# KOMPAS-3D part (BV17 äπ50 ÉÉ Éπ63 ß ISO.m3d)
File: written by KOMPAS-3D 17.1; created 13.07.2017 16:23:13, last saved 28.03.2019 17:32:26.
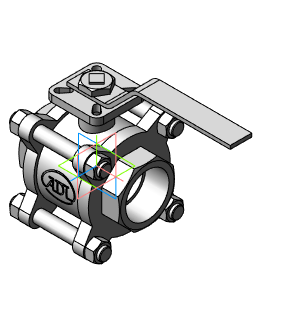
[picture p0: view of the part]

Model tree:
1. Операция без истории:2  (labels: Сталь 20  ГОСТ 1050-88)

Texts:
  DISO1
  DISO2
  BV17 Ду8 1/4" Ру63 с ISO
  BV17 Ду8 СС Ру63 с ISO
  BV17 Ду10 3/8" Ру63 с ISO
  BV17 Ду10 СС Ру63 с ISO
  BV17 Ду15 1/2" Ру63 с ISO
  BV17 Ду15 СС Ру63 с ISO
  BV17 Ду15 ФФ Ру40 с ISO
  BV17 Ду20 3/4" Ру63 с ISO
  BV17 Ду20 СС Ру40 с ISO
  BV17 Ду20 ФФ Ру40 с ISO
  BV17 Ду25 1" Ру63 с ISO
  BV17 Ду25 СС Ру63 с ISO
  BV17 Ду25 ФФ Ру40 с ISO
  BV17 Ду32 1 1/4" Ру63 с ISO
  BV17 Ду32 СС Ру63 с ISO
  BV17 Ду32 ФФ Ру40 с ISO
  BV17 Ду40 1 1/2" Ру63 с ISO
  BV17 Ду40 СС Ру63 с ISO
  BV17 Ду40 ФФ Ру40 с ISO
  BV17 Ду50 2" Ру63 с ISO
  BV17 Ду50 СС Ру63 с ISO
  BV17 Ду50 ФФ Ру40 с ISO
  BV17 Ду65 2 1/2" Ру40 с ISO
  BV17 Ду65 СС Ру40 с ISO
  BV17 Ду65 ФФ Ру40 с ISO
  BV17 Ду80 3" Ру40 с ISO
  BV17 Ду80 СС Ру40 с ISO
  BV17 Ду80 ФФ Ру40 с ISO
  BV17 Ду100 4" Ру40 с ISO
  BV17 Ду100 СС Ру40 с ISO
  BV17 Ду100 ФФ Ру40 с ISO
